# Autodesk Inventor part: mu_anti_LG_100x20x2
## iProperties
Shininess: 64.0
Length Units: 11269
Angle Units: 11279
Time Units: 11290
Mass Units: 11283
Length Display Precision: 3
Angle Display Precision: 2
Compacted: True
Part Number: mu_anti_LG_100x20x2
Document SubType Name: Modeling
Created: 2004-08
Designer: John Blackburn
Manufacturer: Standard
Standards Organization: Custom
Material: Lexan, Clear
Density: 0.0
Volumn: 0.0
Area: 0.0
PropertySet Name: Model Information
Control State: 0
Master: False
Checked Out: False
Author: John Blackburn
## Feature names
1. Loft1
2. Extrusion1
